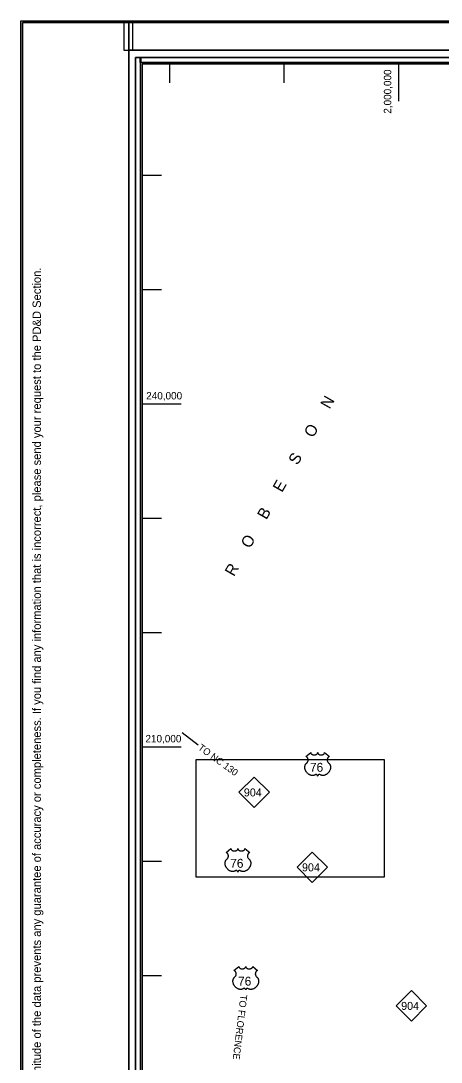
# Model space of a CAD drawing. Extents: x 5197761 to 5514561, y 1890130 to 2080942.
# Drawn here: x 5197761 to 5234499, y 1983827 to 2074930 of the extents above; entities that cross this region are included whole.
import ezdxf

# ---------------------------------------------------------------- set-up
doc = ezdxf.new("R2010")
doc.units = 0
for name, color, linetype in [('Exist Road Primary NC Shield CELL', 7, 'Continuous'), ('Exist Road Primary NC Shield Number Label', 7, 'Continuous'), ('Exist Road Primary US Shield CELL', 7, 'Continuous'), ('Exist Road Primary US Shield Number Label', 7, 'Continuous'), ('Map Preparation Base StatePlane Tick Label', 7, 'Continuous'), ('Map Preparation Base StatePlane Tick Mark', 7, 'Continuous'), ('Map Preparation Border Antique Large Shape', 7, 'Continuous'), ('Map Preparation Border Antique Small Shape', 7, 'Continuous'), ('Map Preparation Border Black Inside Shape', 7, 'Continuous'), ('Map Preparation Border Black Middle Shape', 7, 'Continuous'), ('Map Preparation Border Black Outside Shape', 7, 'Continuous'), ('Map Preparation Border Disclaimer', 7, 'Continuous'), ('Map Preparation County Outside Label', 7, 'Continuous'), ('Map Preparation Destination Label', 7, 'Continuous'), ('Map Preparation Inset Cut Line', 7, 'Continuous')]:
    doc.layers.add(name, color=color, linetype=linetype)

msp = doc.modelspace()

# ---------------------------------------------------------------- linework, layer by layer
at = {"layer": 'Exist Road Primary NC Shield CELL'}
for points in [[(5216817, 2007435), (5218149, 2008767), (5219481, 2007435), (5218149, 2006103)], [(5221900, 2000882), (5223232, 2002214), (5224564, 2000882), (5223232, 1999550)], [(5230568, 1988759), (5231900, 1990091), (5233232, 1988759), (5231900, 1987427)]]:
    msp.add_lwpolyline(points, close=True, dxfattribs=at)
at = {"layer": 'Exist Road Primary US Shield CELL'}
for points in [[(5223098, 2010910), (5223099, 2010892), (5223103, 2010871), (5223106, 2010861), (5223116, 2010840), (5223132, 2010816), (5223155, 2010792), (5223180, 2010771), (5223197, 2010760), (5223226, 2010744), (5223259, 2010730), (5223296, 2010720), (5223333, 2010712), (5223374, 2010708), (5223414, 2010707), (5223458, 2010710), (5223506, 2010720), (5223529, 2010725), (5223553, 2010734), (5223576, 2010744), (5223602, 2010757), (5223622, 2010770), (5223638, 2010782), (5223661, 2010803), (5223679, 2010826), (5223686, 2010838), (5223693, 2010850), (5223702, 2010876), (5223704, 2010887), (5223706, 2010911), (5223707, 2010891), (5223709, 2010879), (5223713, 2010867), (5223718, 2010854), (5223727, 2010836), (5223737, 2010821), (5223756, 2010798), (5223768, 2010787), (5223778, 2010778), (5223807, 2010759), (5223841, 2010742), (5223858, 2010734), (5223875, 2010728), (5223896, 2010722), (5223919, 2010716), (5223941, 2010713), (5223963, 2010709), (5223986, 2010708), (5224005, 2010707), (5224028, 2010707), (5224050, 2010709), (5224071, 2010711), (5224096, 2010715), (5224115, 2010719), (5224141, 2010726), (5224164, 2010734), (5224184, 2010743), (5224210, 2010757), (5224232, 2010770), (5224247, 2010783), (5224266, 2010800), (5224283, 2010820), (5224294, 2010835), (5224301, 2010851), (5224308, 2010867), (5224312, 2010884), (5224314, 2010899), (5224314, 2010911), (5224739, 2010573), (5224729, 2010569), (5224706, 2010557), (5224688, 2010547), (5224659, 2010526), (5224646, 2010515), (5224634, 2010503), (5224622, 2010490), (5224612, 2010479), (5224600, 2010461), (5224589, 2010444), (5224578, 2010426), (5224570, 2010409), (5224557, 2010375), (5224550, 2010353), (5224546, 2010335), (5224541, 2010297), (5224540, 2010279), (5224540, 2010261), (5224541, 2010242), (5224543, 2010224), (5224546, 2010205), (5224549, 2010189), (5224555, 2010169), (5224562, 2010145), (5224571, 2010122), (5224591, 2010085), (5224616, 2010047), (5224634, 2010026), (5224651, 2010008), (5224677, 2009986), (5224692, 2009974), (5224708, 2009957), (5224735, 2009926), (5224745, 2009912), (5224756, 2009895), (5224766, 2009879), (5224776, 2009861), (5224784, 2009845), (5224799, 2009808), (5224810, 2009773), (5224815, 2009754), (5224823, 2009713), (5224826, 2009692), (5224829, 2009651), (5224830, 2009602), (5224826, 2009555), (5224817, 2009501), (5224810, 2009468), (5224799, 2009430), (5224788, 2009397), (5224768, 2009349), (5224751, 2009314), (5224729, 2009273), (5224713, 2009248), (5224696, 2009221), (5224673, 2009190), (5224647, 2009158), (5224616, 2009123), (5224590, 2009098), (5224557, 2009068), (5224537, 2009052), (5224509, 2009030), (5224469, 2009004), (5224431, 2008982), (5224398, 2008965), (5224369, 2008952), (5224331, 2008938), (5224268, 2008921), (5224245, 2008916), (5224218, 2008912), (5224193, 2008909), (5224168, 2008908), (5224135, 2008908), (5224102, 2008910), (5224071, 2008915), (5224039, 2008922), (5224005, 2008932), (5223974, 2008944), (5223943, 2008959), (5223890, 2008992), (5223875, 2009000), (5223867, 2009002), (5223846, 2009003), (5223827, 2008999), (5223808, 2008992), (5223796, 2008985), (5223780, 2008975), (5223768, 2008966), (5223754, 2008952), (5223744, 2008940), (5223736, 2008931), (5223721, 2008908), (5223716, 2008897), (5223710, 2008882), (5223705, 2008861), (5223699, 2008888), (5223691, 2008906), (5223682, 2008921), (5223673, 2008934), (5223658, 2008951), (5223644, 2008964), (5223628, 2008977), (5223611, 2008987), (5223598, 2008994), (5223585, 2008999), (5223570, 2009003), (5223557, 2009004), (5223547, 2009003), (5223533, 2009000), (5223513, 2008986), (5223495, 2008974), (5223475, 2008962), (5223452, 2008949), (5223435, 2008941), (5223414, 2008933), (5223390, 2008925), (5223364, 2008918), (5223337, 2008913), (5223313, 2008909), (5223288, 2008907), (5223265, 2008906), (5223241, 2008906), (5223219, 2008908), (5223193, 2008910), (5223161, 2008915), (5223134, 2008921), (5223106, 2008929), (5223077, 2008938), (5223046, 2008949), (5223008, 2008966), (5222981, 2008980), (5222938, 2009004), (5222889, 2009039), (5222851, 2009069), (5222824, 2009094), (5222783, 2009135), (5222760, 2009162), (5222722, 2009210), (5222698, 2009245), (5222683, 2009271), (5222660, 2009312), (5222648, 2009338), (5222632, 2009376), (5222619, 2009410), (5222609, 2009443), (5222603, 2009464), (5222595, 2009500), (5222590, 2009526), (5222585, 2009561), (5222583, 2009599), (5222582, 2009633), (5222583, 2009662), (5222586, 2009695), (5222592, 2009731), (5222599, 2009761), (5222605, 2009783), (5222614, 2009810), (5222626, 2009839), (5222640, 2009867), (5222653, 2009890), (5222670, 2009916), (5222687, 2009937), (5222708, 2009961), (5222731, 2009982), (5222752, 2009999), (5222776, 2010023), (5222789, 2010038), (5222805, 2010058), (5222817, 2010077), (5222827, 2010094), (5222840, 2010119), (5222847, 2010137), (5222857, 2010166), (5222862, 2010186), (5222867, 2010212), (5222870, 2010236), (5222872, 2010266), (5222871, 2010292), (5222868, 2010321), (5222862, 2010349), (5222855, 2010374), (5222845, 2010402), (5222835, 2010422), (5222819, 2010450), (5222801, 2010476), (5222782, 2010497), (5222763, 2010516), (5222745, 2010530), (5222728, 2010543), (5222706, 2010556), (5222686, 2010566), (5222672, 2010571)], [(5216128, 2002510), (5216129, 2002493), (5216133, 2002472), (5216136, 2002461), (5216146, 2002440), (5216162, 2002416), (5216185, 2002392), (5216210, 2002371), (5216227, 2002360), (5216256, 2002345), (5216289, 2002331), (5216326, 2002320), (5216363, 2002313), (5216404, 2002308), (5216444, 2002308), (5216488, 2002311), (5216536, 2002320), (5216559, 2002326), (5216584, 2002334), (5216607, 2002344), (5216632, 2002358), (5216652, 2002371), (5216668, 2002382), (5216691, 2002404), (5216709, 2002426), (5216716, 2002439), (5216723, 2002451), (5216732, 2002476), (5216734, 2002488), (5216736, 2002511), (5216738, 2002491), (5216740, 2002479), (5216743, 2002467), (5216748, 2002454), (5216757, 2002436), (5216767, 2002421), (5216786, 2002399), (5216798, 2002388), (5216809, 2002379), (5216837, 2002359), (5216871, 2002342), (5216888, 2002335), (5216905, 2002329), (5216926, 2002322), (5216949, 2002317), (5216971, 2002313), (5216993, 2002310), (5217017, 2002308), (5217035, 2002308), (5217058, 2002308), (5217080, 2002309), (5217102, 2002312), (5217126, 2002316), (5217145, 2002320), (5217171, 2002327), (5217194, 2002335), (5217214, 2002344), (5217240, 2002358), (5217262, 2002371), (5217277, 2002383), (5217296, 2002401), (5217314, 2002421), (5217324, 2002436), (5217331, 2002451), (5217338, 2002467), (5217342, 2002484), (5217344, 2002499), (5217344, 2002512), (5217770, 2002173), (5217760, 2002169), (5217736, 2002158), (5217718, 2002147), (5217689, 2002126), (5217676, 2002115), (5217664, 2002103), (5217652, 2002091), (5217642, 2002079), (5217630, 2002062), (5217619, 2002045), (5217608, 2002026), (5217600, 2002010), (5217587, 2001975), (5217581, 2001954), (5217577, 2001936), (5217572, 2001898), (5217570, 2001880), (5217570, 2001862), (5217571, 2001843), (5217573, 2001825), (5217576, 2001806), (5217579, 2001789), (5217585, 2001769), (5217592, 2001745), (5217602, 2001723), (5217621, 2001686), (5217646, 2001648), (5217664, 2001627), (5217681, 2001609), (5217708, 2001587), (5217722, 2001574), (5217738, 2001558), (5217765, 2001527), (5217776, 2001512), (5217786, 2001496), (5217796, 2001479), (5217807, 2001461), (5217815, 2001445), (5217829, 2001409), (5217840, 2001373), (5217845, 2001355), (5217853, 2001313), (5217856, 2001292), (5217860, 2001252), (5217860, 2001203), (5217856, 2001156), (5217847, 2001101), (5217840, 2001069), (5217829, 2001031), (5217818, 2000998), (5217798, 2000949), (5217781, 2000914), (5217759, 2000873), (5217744, 2000848), (5217726, 2000822), (5217703, 2000791), (5217677, 2000758), (5217646, 2000724), (5217621, 2000698), (5217587, 2000669), (5217567, 2000652), (5217539, 2000631), (5217500, 2000604), (5217461, 2000582), (5217428, 2000565), (5217399, 2000553), (5217361, 2000538), (5217298, 2000521), (5217276, 2000516), (5217249, 2000512), (5217223, 2000510), (5217199, 2000508), (5217165, 2000508), (5217133, 2000511), (5217101, 2000515), (5217069, 2000522), (5217035, 2000532), (5217004, 2000544), (5216973, 2000560), (5216921, 2000593), (5216905, 2000601), (5216897, 2000603), (5216877, 2000604), (5216857, 2000600), (5216838, 2000592), (5216826, 2000586), (5216810, 2000576), (5216798, 2000566), (5216784, 2000552), (5216774, 2000541), (5216766, 2000532), (5216751, 2000508), (5216746, 2000497), (5216740, 2000483), (5216736, 2000462), (5216729, 2000488), (5216721, 2000506), (5216712, 2000521), (5216703, 2000534), (5216688, 2000551), (5216675, 2000564), (5216659, 2000577), (5216641, 2000588), (5216628, 2000595), (5216615, 2000599), (5216600, 2000603), (5216587, 2000604), (5216577, 2000604), (5216563, 2000601), (5216544, 2000587), (5216525, 2000574), (5216506, 2000562), (5216482, 2000549), (5216465, 2000541), (5216444, 2000533), (5216420, 2000525), (5216394, 2000519), (5216367, 2000513), (5216343, 2000510), (5216318, 2000507), (5216295, 2000507), (5216271, 2000507), (5216249, 2000509), (5216223, 2000511), (5216191, 2000516), (5216164, 2000522), (5216136, 2000529), (5216107, 2000538), (5216077, 2000550), (5216038, 2000567), (5216011, 2000581), (5215969, 2000605), (5215919, 2000639), (5215881, 2000670), (5215854, 2000695), (5215813, 2000736), (5215790, 2000763), (5215752, 2000811), (5215729, 2000846), (5215713, 2000871), (5215691, 2000913), (5215678, 2000939), (5215662, 2000976), (5215649, 2001011), (5215639, 2001043), (5215633, 2001064), (5215625, 2001101), (5215620, 2001126), (5215615, 2001162), (5215613, 2001199), (5215612, 2001234), (5215613, 2001262), (5215616, 2001296), (5215622, 2001331), (5215629, 2001362), (5215635, 2001383), (5215644, 2001410), (5215656, 2001439), (5215670, 2001468), (5215684, 2001491), (5215700, 2001516), (5215717, 2001537), (5215739, 2001561), (5215761, 2001583), (5215782, 2001599), (5215807, 2001624), (5215819, 2001638), (5215835, 2001658), (5215847, 2001677), (5215857, 2001694), (5215870, 2001719), (5215878, 2001738), (5215887, 2001766), (5215892, 2001786), (5215897, 2001812), (5215901, 2001837), (5215902, 2001867), (5215901, 2001892), (5215898, 2001921), (5215892, 2001950), (5215886, 2001974), (5215875, 2002002), (5215865, 2002023), (5215849, 2002051), (5215831, 2002077), (5215812, 2002098), (5215793, 2002117), (5215775, 2002131), (5215758, 2002143), (5215737, 2002156), (5215716, 2002166), (5215703, 2002172)], [(5216813, 1992195), (5216814, 1992177), (5216818, 1992156), (5216821, 1992145), (5216831, 1992125), (5216847, 1992100), (5216870, 1992077), (5216895, 1992056), (5216912, 1992045), (5216941, 1992029), (5216974, 1992015), (5217011, 1992005), (5217048, 1991997), (5217089, 1991993), (5217130, 1991992), (5217173, 1991995), (5217221, 1992004), (5217244, 1992010), (5217269, 1992019), (5217292, 1992028), (5217317, 1992042), (5217337, 1992055), (5217353, 1992066), (5217376, 1992088), (5217394, 1992110), (5217401, 1992123), (5217408, 1992135), (5217417, 1992161), (5217419, 1992172), (5217421, 1992196), (5217423, 1992176), (5217425, 1992163), (5217428, 1992151), (5217433, 1992139), (5217442, 1992120), (5217452, 1992105), (5217471, 1992083), (5217483, 1992072), (5217494, 1992063), (5217522, 1992043), (5217556, 1992026), (5217573, 1992019), (5217590, 1992013), (5217611, 1992006), (5217634, 1992001), (5217656, 1991997), (5217679, 1991994), (5217702, 1991992), (5217720, 1991992), (5217744, 1991992), (5217765, 1991993), (5217787, 1991996), (5217811, 1992000), (5217830, 1992004), (5217856, 1992011), (5217879, 1992019), (5217899, 1992028), (5217926, 1992042), (5217947, 1992055), (5217962, 1992068), (5217981, 1992085), (5217999, 1992105), (5218009, 1992120), (5218016, 1992135), (5218023, 1992151), (5218027, 1992168), (5218029, 1992183), (5218030, 1992196), (5218455, 1991857), (5218445, 1991853), (5218422, 1991842), (5218403, 1991831), (5218374, 1991811), (5218361, 1991799), (5218349, 1991788), (5218337, 1991775), (5218327, 1991763), (5218315, 1991746), (5218304, 1991729), (5218293, 1991710), (5218285, 1991694), (5218272, 1991660), (5218266, 1991638), (5218262, 1991620), (5218257, 1991582), (5218255, 1991564), (5218255, 1991546), (5218256, 1991527), (5218258, 1991509), (5218261, 1991490), (5218264, 1991474), (5218270, 1991453), (5218277, 1991430), (5218287, 1991407), (5218306, 1991370), (5218331, 1991332), (5218349, 1991311), (5218366, 1991293), (5218393, 1991271), (5218407, 1991258), (5218423, 1991242), (5218450, 1991211), (5218461, 1991197), (5218471, 1991180), (5218482, 1991163), (5218492, 1991145), (5218500, 1991130), (5218515, 1991093), (5218525, 1991058), (5218530, 1991039), (5218538, 1990997), (5218541, 1990977), (5218545, 1990936), (5218545, 1990887), (5218541, 1990840), (5218532, 1990786), (5218525, 1990753), (5218514, 1990715), (5218503, 1990682), (5218484, 1990634), (5218466, 1990598), (5218444, 1990557), (5218429, 1990532), (5218411, 1990506), (5218389, 1990475), (5218362, 1990442), (5218331, 1990408), (5218306, 1990383), (5218273, 1990353), (5218252, 1990336), (5218224, 1990315), (5218185, 1990289), (5218146, 1990266), (5218113, 1990250), (5218084, 1990237), (5218046, 1990223), (5217984, 1990205), (5217961, 1990201), (5217934, 1990197), (5217908, 1990194), (5217884, 1990193), (5217851, 1990193), (5217818, 1990195), (5217786, 1990200), (5217754, 1990206), (5217720, 1990216), (5217689, 1990228), (5217658, 1990244), (5217606, 1990277), (5217591, 1990285), (5217582, 1990287), (5217562, 1990288), (5217543, 1990284), (5217523, 1990276), (5217511, 1990270), (5217495, 1990260), (5217483, 1990250), (5217469, 1990237), (5217459, 1990225), (5217451, 1990216), (5217436, 1990193), (5217431, 1990181), (5217426, 1990167), (5217421, 1990146), (5217414, 1990173), (5217406, 1990190), (5217397, 1990205), (5217388, 1990219), (5217373, 1990236), (5217360, 1990249), (5217344, 1990262), (5217327, 1990272), (5217313, 1990279), (5217300, 1990284), (5217285, 1990288), (5217272, 1990289), (5217262, 1990288), (5217248, 1990285), (5217229, 1990271), (5217211, 1990259), (5217191, 1990246), (5217167, 1990234), (5217150, 1990226), (5217129, 1990218), (5217105, 1990210), (5217079, 1990203), (5217052, 1990198), (5217028, 1990194), (5217003, 1990192), (5216980, 1990191), (5216956, 1990191), (5216934, 1990193), (5216908, 1990195), (5216876, 1990200), (5216849, 1990206), (5216821, 1990213), (5216793, 1990222), (5216762, 1990234), (5216723, 1990251), (5216696, 1990265), (5216654, 1990289), (5216604, 1990324), (5216566, 1990354), (5216539, 1990379), (5216499, 1990420), (5216475, 1990447), (5216438, 1990495), (5216414, 1990530), (5216398, 1990556), (5216376, 1990597), (5216363, 1990623), (5216347, 1990661), (5216334, 1990695), (5216324, 1990728), (5216318, 1990748), (5216310, 1990785), (5216305, 1990811), (5216301, 1990846), (5216298, 1990884), (5216297, 1990918), (5216298, 1990947), (5216302, 1990980), (5216307, 1991015), (5216314, 1991046), (5216320, 1991068), (5216329, 1991094), (5216341, 1991124), (5216355, 1991152), (5216369, 1991175), (5216385, 1991200), (5216402, 1991222), (5216424, 1991245), (5216446, 1991267), (5216467, 1991284), (5216492, 1991308), (5216504, 1991322), (5216520, 1991343), (5216532, 1991362), (5216542, 1991378), (5216555, 1991403), (5216563, 1991422), (5216572, 1991451), (5216577, 1991471), (5216582, 1991497), (5216586, 1991521), (5216587, 1991551), (5216586, 1991576), (5216583, 1991606), (5216577, 1991634), (5216571, 1991659), (5216560, 1991687), (5216550, 1991707), (5216534, 1991735), (5216516, 1991761), (5216497, 1991782), (5216479, 1991801), (5216460, 1991815), (5216443, 1991827), (5216422, 1991840), (5216401, 1991851), (5216388, 1991856)]]:
    msp.add_lwpolyline(points, close=True, dxfattribs=at)
at = {"layer": 'Map Preparation Base StatePlane Tick Mark'}
for p, q in [((5210787, 2069519), (5210787, 2071145)), ((5220787, 2069519), (5220787, 2071145)), ((5230787, 2067894), (5230787, 2071145)), ((5208366, 2061420), (5210065, 2061420)), ((5208366, 2051420), (5210065, 2051420)), ((5208366, 2041420), (5211764, 2041420)), ((5208366, 2031420), (5210065, 2031420)), ((5208366, 2021420), (5210065, 2021420)), ((5208366, 2011420), (5211764, 2011420)), ((5208366, 2001420), (5210065, 2001420)), ((5208366, 1991420), (5210065, 1991420))]:
    msp.add_line(p, q, dxfattribs=at)
at = {"layer": 'Map Preparation Border Antique Large Shape'}
for points in [[(5197907, 2074783), (5207205, 2074783), (5207205, 1892697), (5512539, 1892697), (5512539, 2072359), (5207205, 2072359), (5207205, 2074783), (5514414, 2074783), (5514414, 1890276), (5197907, 1890276)], [(5206760, 2072369), (5207536, 2072369), (5207536, 2074766), (5206760, 2074766)]]:
    msp.add_lwpolyline(points, close=True, dxfattribs=at)
at = {"layer": 'Map Preparation Border Antique Small Shape'}
for points in [[(5207791, 2071720), (5208220, 2071720), (5208220, 1893712), (5511524, 1893712), (5511524, 2071291), (5208220, 2071291), (5208220, 2071720), (5207791, 2071720), (5511953, 2071720), (5511953, 1893283), (5208220, 1893283), (5207791, 1893283)], [(5208167, 2071291), (5208280, 2071291), (5208280, 2071718), (5208167, 2071718)]]:
    msp.add_lwpolyline(points, close=True, dxfattribs=at)
at = {"layer": 'Map Preparation Border Black Inside Shape'}
msp.add_lwpolyline([(5208220, 2071291), (5511524, 2071291), (5511524, 1893712), (5208366, 1893712), (5208366, 1893858), (5511378, 1893858), (5511378, 2071145), (5208366, 2071145), (5208366, 1893858), (5208366, 1893712), (5208220, 1893712), (5208220, 1893858)], close=True, dxfattribs=at)
at = {"layer": 'Map Preparation Border Black Middle Shape'}
msp.add_lwpolyline([(5207205, 2072359), (5512539, 2072359), (5512539, 1892697), (5511953, 1892697), (5207791, 1892697), (5207791, 1893283), (5511953, 1893283), (5511953, 2071720), (5207791, 2071720), (5207791, 1892697), (5207205, 1892697)], close=True, dxfattribs=at)
at = {"layer": 'Map Preparation Border Black Outside Shape'}
msp.add_lwpolyline([(5197761, 2074930), (5514561, 2074930), (5514561, 1890130), (5197907, 1890130), (5197907, 1890276), (5514414, 1890276), (5514414, 2074783), (5197907, 2074783), (5197907, 1890130), (5197761, 1890130)], close=True, dxfattribs=at)
at = {"layer": 'Map Preparation Destination Label'}
msp.add_line((5211857, 2012661), (5213247, 2011588), dxfattribs=at)
at = {"layer": 'Map Preparation Inset Cut Line'}
msp.add_lwpolyline([(5213088, 2010312), (5229518, 2010312), (5229518, 2000010), (5213088, 2000010)], close=True, dxfattribs=at)

# ---------------------------------------------------------------- texts
at = {"layer": 'Exist Road Primary NC Shield Number Label'}
for p in [(5217253, 2007076), (5222337, 2000523), (5231004, 1988400)]:
    msp.add_text('904', height=700, dxfattribs=at).set_placement(p)
at = {"layer": 'Exist Road Primary US Shield Number Label'}
for p in [(5223029, 2009235), (5216059, 2000835), (5216744, 1990520)]:
    msp.add_text('76', height=780, dxfattribs=at).set_placement(p)
at = {"layer": 'Map Preparation Base StatePlane Tick Label'}
msp.add_text('2,000,000', height=650, rotation=90, dxfattribs=at).set_placement((5230138, 2066806))
for s, p in [('240,000', (5208718, 2041807)), ('210,000', (5208652, 2011807))]:
    msp.add_text(s, height=650, dxfattribs=at).set_placement(p)
at = {"layer": 'Map Preparation Border Disclaimer'}
msp.add_text("Disclaimer: The PD&D's goal is to provide the most accurate information as possible. The magnitude of the data prevents any guarantee of accuracy or completeness. If you find any information that is incorrect, please send your request to the PD&D Section.", height=730, rotation=90, dxfattribs=at).set_placement((5199514, 1942196))
at = {"layer": 'Map Preparation County Outside Label'}
msp.add_text('R     O     B     E     S     O     N', height=1000, rotation=60.30953, dxfattribs=at).set_placement((5216392, 2026256))
at = {"layer": 'Map Preparation Destination Label'}
for s, rotation, p in [('TO NC 130', 323.80089, (5213195, 2011224)), ('TO FLORENCE', 263.22835, (5216957, 1989752))]:
    msp.add_text(s, height=600, rotation=rotation, dxfattribs=at).set_placement(p)

doc.saveas('drawing.dxf')
